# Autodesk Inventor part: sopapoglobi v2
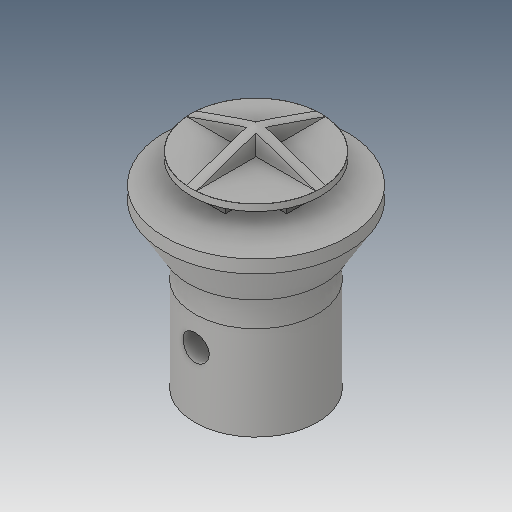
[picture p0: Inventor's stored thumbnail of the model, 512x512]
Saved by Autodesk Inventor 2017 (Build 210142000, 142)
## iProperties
Created: 2018-08
Part Number: sopapoglobi v2
Material: Plastic, Opaque Black
Document SubType Name: Modeling
Designer: JK
Density: 0.952 g/cm^3
Appearance: Smooth - Black
Sending System: Autodesk Translation Framework v7.1.0.215
Preprocessor: ST-DEVELOPER v17
Title: C:/Users/FabLab/Desktop/sopapoglobi v2.step
Author: golave@ing.uchile.cl
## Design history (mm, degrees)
feature "Body1"
body "Solid1"
